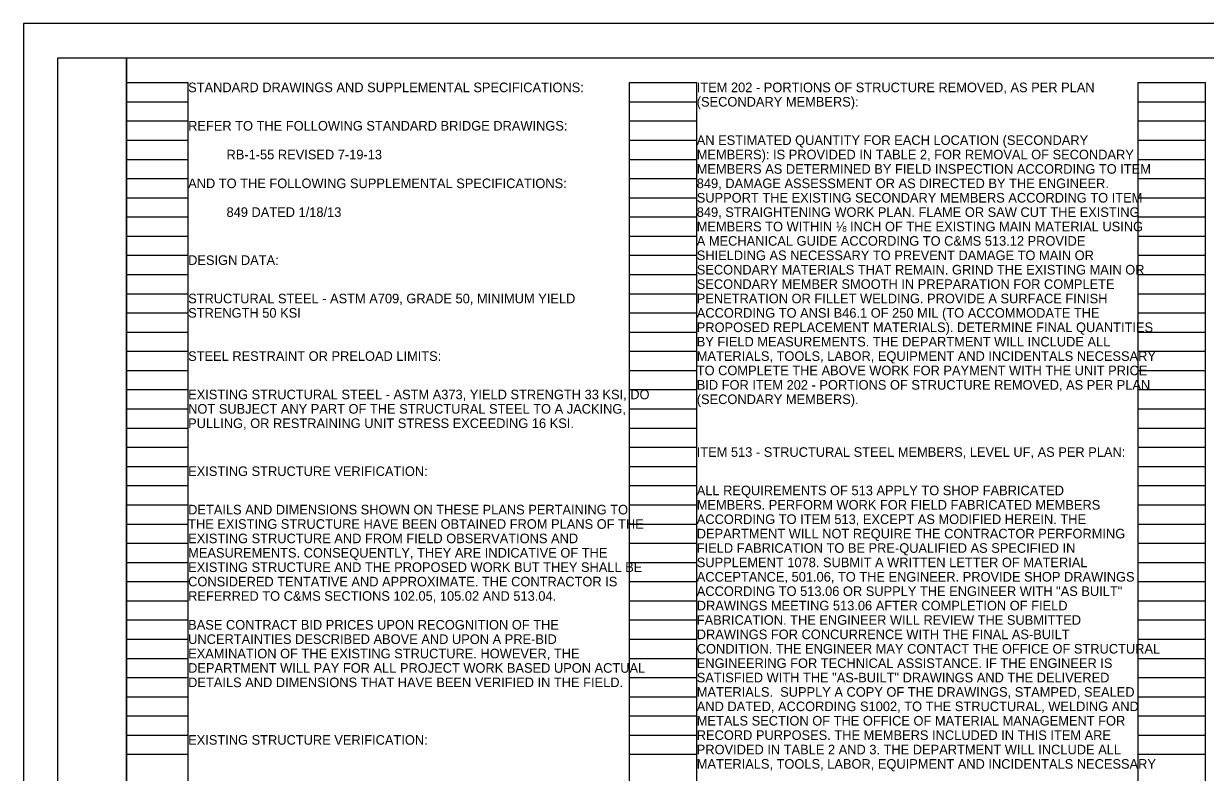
# Model space of a CAD drawing. Extents: x 0 to 34, y -1.2 to 22.
# Drawn here: x 0 to 17.24, y 11.08 to 22 of the extents above; entities that cross this region are included whole.
import ezdxf

# ---------------------------------------------------------------- set-up
doc = ezdxf.new("R2010")
doc.units = 0
for name, color, linetype in [('SH_Border', 7, 'Continuous'), ('SH_Cut_Line', 7, 'Continuous'), ('SH_Data', 7, 'Continuous'), ('ST_Details', 7, 'Continuous'), ('ST_Text', 7, 'Continuous')]:
    doc.layers.add(name, color=color, linetype=linetype)

msp = doc.modelspace()

# ---------------------------------------------------------------- linework, layer by layer
at = {"layer": 'SH_Data'}
for p, q in [((1.5, 0.98), (1.5, 21.14)), ((1.5, 21.14), (2.4, 21.14)), ((2.4, 0.98), (2.4, 21.14)), ((8.84, 0.98), (8.84, 21.14)), ((8.84, 21.14), (9.82, 21.14)), ((9.82, 0.98), (9.82, 21.14)), ((16.26, 0.98), (16.26, 21.14)), ((16.26, 21.14), (17.24, 21.14)), ((17.24, 0.98), (17.24, 21.14)), ((1.5, 20.86), (2.4, 20.86)), ((8.84, 20.86), (9.82, 20.86)), ((16.26, 20.86), (17.24, 20.86)), ((1.5, 20.58), (2.4, 20.58)), ((8.84, 20.58), (9.82, 20.58)), ((16.26, 20.58), (17.24, 20.58)), ((1.5, 20.3), (2.4, 20.3)), ((8.84, 20.3), (9.82, 20.3)), ((16.26, 20.3), (17.24, 20.3)), ((1.5, 20.02), (2.4, 20.02)), ((8.84, 20.02), (9.82, 20.02)), ((16.26, 20.02), (17.24, 20.02)), ((1.5, 19.74), (2.4, 19.74)), ((8.84, 19.74), (9.82, 19.74)), ((16.26, 19.74), (17.24, 19.74)), ((1.5, 19.46), (2.4, 19.46)), ((8.84, 19.46), (9.82, 19.46)), ((16.26, 19.46), (17.24, 19.46)), ((1.5, 19.18), (2.4, 19.18)), ((8.84, 19.18), (9.82, 19.18)), ((16.26, 19.18), (17.24, 19.18)), ((1.5, 18.9), (2.4, 18.9)), ((8.84, 18.9), (9.82, 18.9)), ((16.26, 18.9), (17.24, 18.9)), ((1.5, 18.62), (2.4, 18.62)), ((8.84, 18.62), (9.82, 18.62)), ((16.26, 18.62), (17.24, 18.62)), ((1.5, 18.34), (2.4, 18.34)), ((8.84, 18.34), (9.82, 18.34)), ((16.26, 18.34), (17.24, 18.34)), ((1.5, 18.06), (2.4, 18.06)), ((8.84, 18.06), (9.82, 18.06)), ((16.26, 18.06), (17.24, 18.06)), ((1.5, 17.78), (2.4, 17.78)), ((8.84, 17.78), (9.82, 17.78)), ((16.26, 17.78), (17.24, 17.78)), ((1.5, 17.5), (2.4, 17.5)), ((8.84, 17.5), (9.82, 17.5)), ((16.26, 17.5), (17.24, 17.5)), ((1.5, 17.22), (2.4, 17.22)), ((8.84, 17.22), (9.82, 17.22)), ((16.26, 17.22), (17.24, 17.22)), ((1.5, 16.94), (2.4, 16.94)), ((8.84, 16.94), (9.82, 16.94)), ((16.26, 16.94), (17.24, 16.94)), ((1.5, 16.66), (2.4, 16.66)), ((8.84, 16.66), (9.82, 16.66)), ((16.26, 16.66), (17.24, 16.66)), ((1.5, 16.38), (2.4, 16.38)), ((8.84, 16.38), (9.82, 16.38)), ((16.26, 16.38), (17.24, 16.38)), ((1.5, 16.1), (2.4, 16.1)), ((8.84, 16.1), (9.82, 16.1)), ((16.26, 16.1), (17.24, 16.1)), ((1.5, 15.82), (2.4, 15.82)), ((8.84, 15.82), (9.82, 15.82)), ((16.26, 15.82), (17.24, 15.82)), ((1.5, 15.54), (2.4, 15.54)), ((8.84, 15.54), (9.82, 15.54)), ((16.26, 15.54), (17.24, 15.54)), ((1.5, 15.26), (2.4, 15.26)), ((8.84, 15.26), (9.82, 15.26)), ((16.26, 15.26), (17.24, 15.26)), ((1.5, 14.98), (2.4, 14.98)), ((8.84, 14.98), (9.82, 14.98)), ((16.26, 14.98), (17.24, 14.98)), ((1.5, 14.7), (2.4, 14.7)), ((8.84, 14.7), (9.82, 14.7)), ((16.26, 14.7), (17.24, 14.7)), ((1.5, 14.42), (2.4, 14.42)), ((8.84, 14.42), (9.82, 14.42)), ((16.26, 14.42), (17.24, 14.42)), ((1.5, 14.14), (2.4, 14.14)), ((8.84, 14.14), (9.82, 14.14)), ((16.26, 14.14), (17.24, 14.14)), ((1.5, 13.86), (2.4, 13.86)), ((8.84, 13.86), (9.82, 13.86)), ((16.26, 13.86), (17.24, 13.86)), ((1.5, 13.58), (2.4, 13.58)), ((8.84, 13.58), (9.82, 13.58)), ((16.26, 13.58), (17.24, 13.58)), ((1.5, 13.3), (2.4, 13.3)), ((8.84, 13.3), (9.82, 13.3)), ((16.26, 13.3), (17.24, 13.3)), ((1.5, 13.02), (2.4, 13.02)), ((8.84, 13.02), (9.82, 13.02)), ((16.26, 13.02), (17.24, 13.02)), ((1.5, 12.74), (2.4, 12.74)), ((8.84, 12.74), (9.82, 12.74)), ((16.26, 12.74), (17.24, 12.74)), ((1.5, 12.46), (2.4, 12.46)), ((8.84, 12.46), (9.82, 12.46)), ((16.26, 12.46), (17.24, 12.46)), ((1.5, 12.18), (2.4, 12.18)), ((8.84, 12.18), (9.82, 12.18)), ((16.26, 12.18), (17.24, 12.18)), ((1.5, 11.9), (2.4, 11.9)), ((8.84, 11.9), (9.82, 11.9)), ((16.26, 11.9), (17.24, 11.9)), ((1.5, 11.62), (2.4, 11.62)), ((8.84, 11.62), (9.82, 11.62)), ((16.26, 11.62), (17.24, 11.62)), ((1.5, 11.34), (2.4, 11.34)), ((8.84, 11.34), (9.82, 11.34)), ((16.26, 11.34), (17.24, 11.34))]:
    msp.add_line(p, q, dxfattribs=at)
at = {"layer": 'ST_Details'}
msp.add_lwpolyline([(0, 0), (34, 0), (34, 22), (0, 22)], close=True, dxfattribs=at)
at = {"layer": 'ST_Text'}
for points in [[(0.5, 21.5), (1.5, 21.5), (1.5, 0.5), (0.5, 0.5)], [(1.5, 21.5), (33.5, 21.5), (33.5, 0.5), (1.5, 0.5)]]:
    msp.add_lwpolyline(points, close=True, dxfattribs=at)

# ---------------------------------------------------------------- texts
at = {"layer": 'SH_Border'}
for s, p in [('ITEM 202 - PORTIONS OF STRUCTURE REMOVED, AS PER PLAN ', (9.82, 21)), ('(SECONDARY MEMBERS): ', (9.82, 20.79)), ('ITEM 513 - STRUCTURAL STEEL MEMBERS, LEVEL UF, AS PER PLAN:', (9.82, 15.68)), ('EXISTING STRUCTURE VERIFICATION:', (2.4, 11.48))]:
    msp.add_text(s, height=0.14, dxfattribs=at).set_placement(p)
at = {"layer": 'SH_Cut_Line'}
for s, p in [('STANDARD DRAWINGS AND SUPPLEMENTAL SPECIFICATIONS:', (2.4, 21)), ('REFER TO THE FOLLOWING STANDARD BRIDGE DRAWINGS:', (2.4, 20.44)), ('AN ESTIMATED QUANTITY FOR EACH LOCATION (SECONDARY ', (9.82, 20.23)), ('RB-1-55 REVISED 7-19-13', (2.96, 20.02)), ('MEMBERS): IS PROVIDED IN TABLE 2, FOR REMOVAL OF SECONDARY ', (9.82, 20.02)), ('MEMBERS AS DETERMINED BY FIELD INSPECTION ACCORDING TO ITEM ', (9.82, 19.81)), ('AND TO THE FOLLOWING SUPPLEMENTAL SPECIFICATIONS:', (2.4, 19.6)), ('849, DAMAGE ASSESSMENT OR AS DIRECTED BY THE ENGINEER.  ', (9.82, 19.6)), ('SUPPORT THE EXISTING SECONDARY MEMBERS ACCORDING TO ITEM ', (9.82, 19.39)), ('849 DATED 1/18/13', (2.96, 19.18)), ('849, STRAIGHTENING WORK PLAN. FLAME OR SAW CUT THE EXISTING ', (9.82, 19.18)), ('MEMBERS TO WITHIN ⅛ INCH OF THE EXISTING MAIN MATERIAL USING ', (9.82, 18.97)), ('A MECHANICAL GUIDE ACCORDING TO C&MS 513.12 PROVIDE ', (9.82, 18.76)), ('DESIGN DATA:', (2.4, 18.48)), ('SHIELDING AS NECESSARY TO PREVENT DAMAGE TO MAIN OR ', (9.82, 18.55)), ('SECONDARY MATERIALS THAT REMAIN. GRIND THE EXISTING MAIN OR ', (9.82, 18.34)), ('SECONDARY MEMBER SMOOTH IN PREPARATION FOR COMPLETE ', (9.82, 18.13)), ('STRUCTURAL STEEL - ASTM A709, GRADE 50, MINIMUM YIELD ', (2.4, 17.92)), ('PENETRATION OR FILLET WELDING. PROVIDE A SURFACE FINISH ', (9.82, 17.92)), ('STRENGTH 50 KSI', (2.4, 17.71)), ('ACCORDING TO ANSI B46.1 OF 250 MIL (TO ACCOMMODATE THE ', (9.82, 17.71)), ('PROPOSED REPLACEMENT MATERIALS). DETERMINE FINAL QUANTITIES ', (9.82, 17.5)), ('BY FIELD MEASUREMENTS. THE DEPARTMENT WILL INCLUDE ALL ', (9.82, 17.29)), ('STEEL RESTRAINT OR PRELOAD LIMITS:', (2.4, 17.08)), ('MATERIALS, TOOLS, LABOR, EQUIPMENT AND INCIDENTALS NECESSARY ', (9.82, 17.08)), ('TO COMPLETE THE ABOVE WORK FOR PAYMENT WITH THE UNIT PRICE ', (9.82, 16.87)), ('BID FOR ITEM 202 - PORTIONS OF STRUCTURE REMOVED, AS PER PLAN ', (9.82, 16.66)), ('EXISTING STRUCTURAL STEEL - ASTM A373, YIELD STRENGTH 33 KSI, DO ', (2.4, 16.52)), ('(SECONDARY MEMBERS).', (9.82, 16.45)), ('NOT SUBJECT ANY PART OF THE STRUCTURAL STEEL TO A JACKING, ', (2.4, 16.31)), ('PULLING, OR RESTRAINING UNIT STRESS EXCEEDING 16 KSI.', (2.4, 16.1)), ('EXISTING STRUCTURE VERIFICATION:', (2.4, 15.4)), ('ALL REQUIREMENTS OF 513 APPLY TO SHOP FABRICATED ', (9.82, 15.12)), ('MEMBERS. PERFORM WORK FOR FIELD FABRICATED MEMBERS ', (9.82, 14.91)), ('DETAILS AND DIMENSIONS SHOWN ON THESE PLANS PERTAINING TO ', (2.4, 14.84)), ('ACCORDING TO ITEM 513, EXCEPT AS MODIFIED HEREIN. THE ', (9.82, 14.7)), ('THE EXISTING STRUCTURE HAVE BEEN OBTAINED FROM PLANS OF THE ', (2.4, 14.63)), ('EXISTING STRUCTURE AND FROM FIELD OBSERVATIONS AND ', (2.4, 14.42)), ('DEPARTMENT WILL NOT REQUIRE THE CONTRACTOR PERFORMING ', (9.82, 14.49)), ('MEASUREMENTS. CONSEQUENTLY, THEY ARE INDICATIVE OF THE ', (2.4, 14.21)), ('FIELD FABRICATION TO BE PRE-QUALIFIED AS SPECIFIED IN ', (9.82, 14.28)), ('EXISTING STRUCTURE AND THE PROPOSED WORK BUT THEY SHALL BE ', (2.4, 14)), ('SUPPLEMENT 1078. SUBMIT A WRITTEN LETTER OF MATERIAL ', (9.82, 14.07)), ('ACCEPTANCE, 501.06, TO THE ENGINEER. PROVIDE SHOP DRAWINGS ', (9.82, 13.86)), ('CONSIDERED TENTATIVE AND APPROXIMATE. THE CONTRACTOR IS ', (2.4, 13.79)), ('REFERRED TO C&MS SECTIONS 102.05, 105.02 AND 513.04. ', (2.4, 13.58)), ('ACCORDING TO 513.06 OR SUPPLY THE ENGINEER WITH "AS BUILT" ', (9.82, 13.65)), ('DRAWINGS MEETING 513.06 AFTER COMPLETION OF FIELD ', (9.82, 13.44)), ('BASE CONTRACT BID PRICES UPON RECOGNITION OF THE ', (2.4, 13.16)), ('FABRICATION. THE ENGINEER WILL REVIEW THE SUBMITTED ', (9.82, 13.23)), ('DRAWINGS FOR CONCURRENCE WITH THE FINAL AS-BUILT ', (9.82, 13.02)), ('UNCERTAINTIES DESCRIBED ABOVE AND UPON A PRE-BID ', (2.4, 12.95)), ('CONDITION. THE ENGINEER MAY CONTACT THE OFFICE OF STRUCTURAL ', (9.82, 12.81)), ('EXAMINATION OF THE EXISTING STRUCTURE. HOWEVER, THE ', (2.4, 12.74)), ('DEPARTMENT WILL PAY FOR ALL PROJECT WORK BASED UPON ACTUAL ', (2.4, 12.53)), ('ENGINEERING FOR TECHNICAL ASSISTANCE. IF THE ENGINEER IS ', (9.82, 12.6)), ('DETAILS AND DIMENSIONS THAT HAVE BEEN VERIFIED IN THE FIELD.', (2.4, 12.32)), ('SATISFIED WITH THE "AS-BUILT" DRAWINGS AND THE DELIVERED ', (9.82, 12.39)), ('MATERIALS.  SUPPLY A COPY OF THE DRAWINGS, STAMPED, SEALED ', (9.82, 12.18)), ('AND DATED, ACCORDING S1002, TO THE STRUCTURAL, WELDING AND ', (9.82, 11.97)), ('METALS SECTION OF THE OFFICE OF MATERIAL MANAGEMENT FOR ', (9.82, 11.76)), ('RECORD PURPOSES. THE MEMBERS INCLUDED IN THIS ITEM ARE ', (9.82, 11.55)), ('PROVIDED IN TABLE 2 AND 3. THE DEPARTMENT WILL INCLUDE ALL ', (9.82, 11.34)), ('MATERIALS, TOOLS, LABOR, EQUIPMENT AND INCIDENTALS NECESSARY ', (9.82, 11.13))]:
    msp.add_text(s, height=0.14, dxfattribs=at).set_placement(p)

doc.saveas('drawing.dxf')
